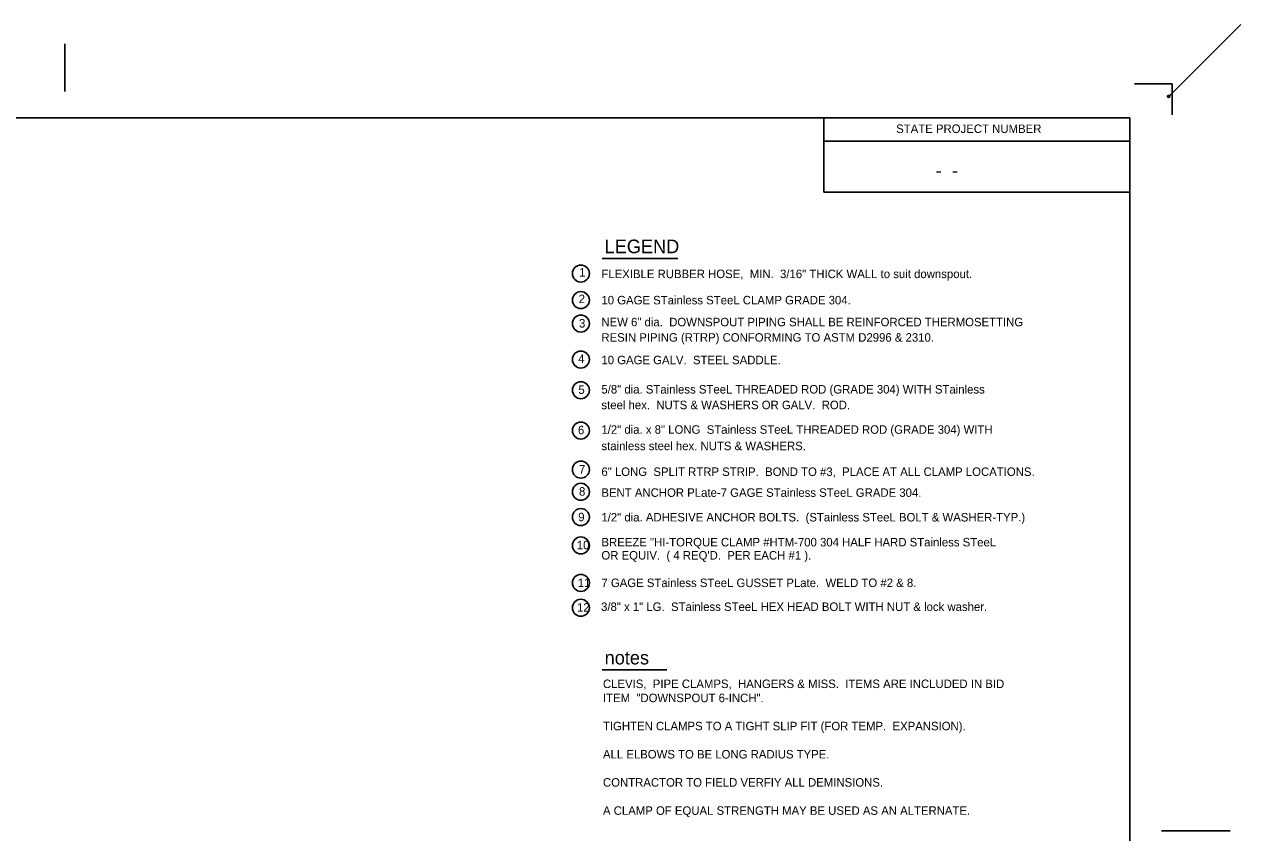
# Model space of a CAD drawing. Extents: x 15000 to 15012.1, y 999.8 to 1007.9.
# Drawn here: x 15006.08 to 15012.05, y 1003.78 to 1007.74 of the extents above; entities that cross this region are included whole.
import ezdxf

# ---------------------------------------------------------------- set-up
doc = ezdxf.new("R2010")
doc.units = 0
for name, color, linetype in [('b_title text', 7, 'Continuous'), ('Level 1', 7, 'Continuous'), ('Level 2', 7, 'Continuous'), ('Level 37', 7, 'Continuous'), ('Level 49', 7, 'Continuous')]:
    doc.layers.add(name, color=color, linetype=linetype)

msp = doc.modelspace()

# ---------------------------------------------------------------- linework, layer by layer
at = {"layer": 'b_title text'}
for p, q in [((15008.9179, 1006.5914), (15009.2894, 1006.5914)), ((15008.9179, 1004.5751), (15009.2351, 1004.5751))]:
    msp.add_line(p, q, dxfattribs=at)
at = {"layer": 'Level 1'}
for p, q in [((15011.714, 1007.4479), (15011.5294, 1007.4479)), ((15011.714, 1007.2964), (15011.714, 1007.4479)), ((15011.5058, 1007.2814), (15001.0578, 1007.2814)), ((15010.0053, 1007.2814), (15010.0053, 1006.9166)), ((15011.5058, 1000.2885), (15011.5058, 1007.2814)), ((15010.0053, 1007.1667), (15011.5058, 1007.1667)), ((15010.0053, 1006.9166), (15011.5058, 1006.9166))]:
    msp.add_line(p, q, dxfattribs=at)
at = {"layer": 'Level 2'}
msp.add_line((15011.697, 1007.3865), (15012.0502, 1007.7397), dxfattribs=at)
for centre in [(15008.8132, 1006.5177), (15008.8132, 1006.3875), (15008.8132, 1006.2729), (15008.8132, 1006.0963), (15008.8132, 1005.9458), (15008.8132, 1005.748), (15008.8132, 1005.5565), (15008.8132, 1005.4481), (15008.8132, 1005.3241), (15008.8132, 1005.1846), (15008.8132, 1005.001), (15008.8132, 1004.8789)]:
    msp.add_circle(centre, 0.0417, dxfattribs=at)
at = {"layer": 'Level 37'}
for p, q in [((15006.2818, 1007.4105), (15006.2818, 1007.6437)), ((15011.6624, 1003.7849), (15011.9988, 1003.7849))]:
    msp.add_line(p, q, dxfattribs=at)
at = {"layer": 'Level 49'}
msp.add_circle((15011.6969, 1007.3865), 0.00506, dxfattribs=at)

# ---------------------------------------------------------------- texts
at = {"layer": 'b_title text'}
for s, p in [('LEGEND', (15008.9299, 1006.6176)), ('notes', (15008.9299, 1004.6013))]:
    msp.add_text(s, height=0.0666, dxfattribs=at).set_placement(p)
at = {"layer": 'Level 1'}
for s, height, p in [('STATE PROJECT NUMBER', 0.041708, (15010.36, 1007.2069)), ('    -  -  ', 0.06735, (15010.4538, 1006.9895))]:
    msp.add_text(s, height=height, dxfattribs=at).set_placement(p)
at = {"layer": 'Level 2'}
for s, height, p in [('1', 0.0417, (15008.805, 1006.5031)), ('FLEXIBLE RUBBER HOSE,  MIN.  3/16" THICK WALL to suit downspout.', 0.041667, (15008.9141, 1006.4954)), ('2', 0.0417, (15008.8025, 1006.3729)), ('10 GAGE STainless STeeL CLAMP GRADE 304.', 0.041667, (15008.9141, 1006.3666)), ('3', 0.0417, (15008.8042, 1006.2532)), ('NEW 6" dia.  DOWNSPOUT PIPING SHALL BE REINFORCED THERMOSETTING', 0.041667, (15008.9141, 1006.2592)), ('RESIN PIPING (RTRP) CONFORMING TO ASTM D2996 & 2310.', 0.041667, (15008.9141, 1006.1838)), ('4', 0.0417, (15008.8003, 1006.0793)), ('10 GAGE GALV.  STEEL SADDLE.', 0.041667, (15008.9141, 1006.0731)), ('5', 0.0417, (15008.8013, 1005.9277)), ('5/8" dia. STainless STeeL THREADED ROD (GRADE 304) WITH STainless', 0.041667, (15008.9141, 1005.9295)), ('steel hex.  NUTS & WASHERS OR GALV.  ROD.', 0.041667, (15008.9141, 1005.8527)), ('6', 0.0417, (15008.799, 1005.7298)), ('1/2" dia. x 8" LONG  STainless STeeL THREADED ROD (GRADE 304) WITH', 0.041667, (15008.9141, 1005.7323)), ('stainless steel hex. NUTS & WASHERS. ', 0.041667, (15008.9141, 1005.6518)), ('7', 0.0417, (15008.804, 1005.5372)), ('6" LONG  SPLIT RTRP STRIP.  BOND TO #3,  PLACE AT ALL CLAMP LOCATIONS.', 0.041667, (15008.9141, 1005.5254)), ('8', 0.0417, (15008.8043, 1005.4288)), ('BENT ANCHOR PLate-7 GAGE STainless STeeL GRADE 304.', 0.041667, (15008.9141, 1005.4231)), ('9', 0.0417, (15008.8003, 1005.3034)), ('1/2" dia. ADHESIVE ANCHOR BOLTS.  (STainless STeeL BOLT & WASHER-TYP.)', 0.041667, (15008.9141, 1005.3023)), ('10', 0.04167, (15008.7931, 1005.1657)), ('BREEZE "HI-TORQUE CLAMP #HTM-700 304 HALF HARD STainless STeeL', 0.041667, (15008.9141, 1005.18)), ("OR EQUIV.  ( 4 REQ'D.  PER EACH #1 ).", 0.041667, (15008.9141, 1005.1156)), ('11', 0.04167, (15008.7978, 1004.9807)), ('7 GAGE STainless STeeL GUSSET PLate.  WELD TO #2 & 8.', 0.041667, (15008.9141, 1004.9806)), ('12', 0.04167, (15008.7944, 1004.86)), ('3/8" x 1" LG.  STainless STeeL HEX HEAD BOLT WITH NUT & lock washer.', 0.041667, (15008.9124, 1004.8634)), ('CLEVIS,  PIPE CLAMPS,  HANGERS & MISS.  ITEMS ARE INCLUDED IN BID', 0.041651, (15008.9218, 1004.4855)), ('ITEM  "DOWNSPOUT 6-INCH".', 0.041651, (15008.9218, 1004.4164)), ('TIGHTEN CLAMPS TO A TIGHT SLIP FIT (FOR TEMP.  EXPANSION).', 0.041651, (15008.9218, 1004.2783)), ('ALL ELBOWS TO BE LONG RADIUS TYPE.', 0.041651, (15008.9218, 1004.1402)), ('CONTRACTOR TO FIELD VERFIY ALL DEMINSIONS.', 0.041651, (15008.9218, 1004.0021)), ('A CLAMP OF EQUAL STRENGTH MAY BE USED AS AN ALTERNATE.', 0.041651, (15008.9218, 1003.864))]:
    msp.add_text(s, height=height, dxfattribs=at).set_placement(p)

doc.saveas('drawing.dxf')
